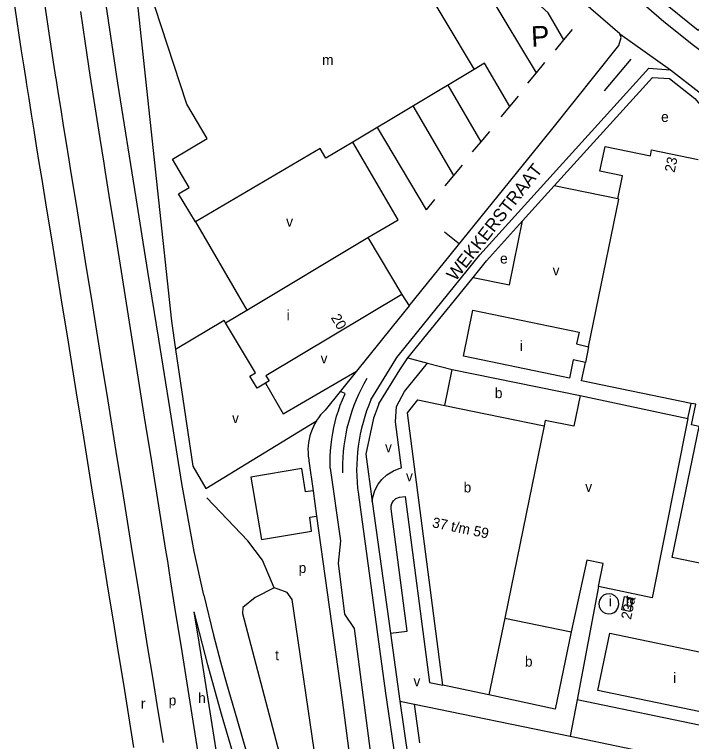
# Model space of a CAD drawing. Extents: x 157699 to 159683, y 381451 to 383293.
# Drawn here: x 157713.1 to 157977.1, y 382628.7 to 382912.1 of the extents above; entities that cross this region are included whole.
import ezdxf

# ---------------------------------------------------------------- set-up
doc = ezdxf.new("R2010")
doc.units = 0
for name, color, linetype in [('BLT_Basislijn', 7, 'Continuous'), ('BLT_Bebouwing', 7, 'Continuous'), ('BLT_Centroide', 7, 'Continuous'), ('BLT_Huisnummer', 7, 'Continuous'), ('BLT_Huisnummer_reeks', 7, 'Continuous'), ('BLT_Onderdoorgang_en_onderverdeling', 7, 'Continuous'), ('BLT_Onderverdeling_panden', 7, 'Continuous'), ('BLT_Straatnaam', 7, 'Continuous'), ('BLT_Tekst_parkeren', 7, 'Continuous'), ('BLT_Vlakafsluiter', 7, 'Continuous')]:
    doc.layers.add(name, color=color, linetype=linetype)

msp = doc.modelspace()

# ---------------------------------------------------------------- linework, layer by layer
at = {"layer": 'BLT_Basislijn'}
for p, q in [((157927.35, 382902.27), (157930.7, 382906.28)), ((157923.99, 382898.25), (157927.35, 382902.27)), ((157916.6, 382889.41), (157919.95, 382893.42)), ((157953.48, 382894.63), (157943.06, 382882.29)), ((157913.25, 382885.39), (157916.6, 382889.41)), ((157895.1, 382862.52), (157882.18, 382884.61)), ((157906.25, 382876.23), (157909.6, 382880.24)), ((157884.44, 382849.34), (157868.59, 382876.47)), ((157902.9, 382872.22), (157906.25, 382876.23)), ((157873.71, 382835.98), (157854.6, 382868.08)), ((157895.1, 382862.52), (157898.45, 382866.53)), ((157891.74, 382858.5), (157895.1, 382862.52)), ((157884.44, 382849.34), (157887.8, 382853.35)), ((157881.09, 382845.32), (157884.44, 382849.34)), ((157948.3, 382840.19), (157923.57, 382845.28)), ((157873.71, 382835.98), (157877.06, 382840)), ((157783.62, 382831.27), (157803.71, 382796.88)), ((157880.8, 382827.41), (157886.6, 382822.68)), ((157864.14, 382803.01), (157867.03, 382798.53)), ((157860.37, 382790.28), (157846.47, 382773.07)), ((157846.47, 382773.07), (157840.08, 382765.15)), ((157840.08, 382765.15), (157834.24, 382757.92)), ((157842.01, 382764.35), (157840.08, 382765.15)), ((157933.67, 382763.53), (157975.66, 382754.55)), ((157975.66, 382754.55), (157976.89, 382760.52)), ((157787.7, 382727.37), (157830.8, 382753.65)), ((157850.07, 382740.75), (157852.61, 382722.31)), ((157827.93, 382738.12), (157829.54, 382726.45)), ((157829.54, 382726.45), (157830.92, 382716.53)), ((157847.21, 382724.81), (157857.82, 382647.47)), ((157852.61, 382722.31), (157859.68, 382670.86)), ((157830.92, 382716.53), (157840.85, 382644.96)), ((157845.48, 382672.76), (157853.96, 382608.2)), ((157859.68, 382670.86), (157863.31, 382644.46)), ((157857.82, 382647.47), (157864.76, 382599.52)), ((157840.85, 382644.96), (157847.02, 382597.39)), ((157863.31, 382644.46), (157869.03, 382643.28)), ((157863.31, 382644.46), (157869.71, 382600.22)), ((157871.21, 382628.11), (157869.03, 382643.28)), ((157869.03, 382643.28), (157929.77, 382630.74)), ((158007.7, 382629.31), (157932.45, 382644.98)), ((157929.77, 382630.74), (157993.12, 382617.66))]:
    msp.add_line(p, q, dxfattribs=at)
for points in [[(157949.07, 382904.54), (157934.04, 382917.51), (157923.29, 382927.29), (157910.32, 382940.07), (157892.3, 382958.54), (157858.2, 382996.52), (157853.38, 383002.06)], [(157916.6, 382889.41), (157873.89, 382960.49), (157865.17, 382970), (157863.48, 382969.01)], [(157757.42, 382949.97), (157774.26, 382792.55), (157775.91, 382781.48)], [(158004.65, 382879.91), (157977.9, 382900), (157966.26, 382909.27), (157938.29, 382933.57)], [(157927.35, 382902.27), (157921.19, 382912.79), (157910, 382923.04), (157909.38, 382922.68)], [(157724.5, 382918.05), (157725.4, 382911.91), (157726.32, 382905.77), (157727.26, 382899.63), (157728.2, 382893.48), (157729.11, 382887.69), (157729.17, 382887.33), (157730.14, 382881.18), (157731.12, 382875.02), (157732.11, 382868.86), (157733.1, 382862.7), (157734.27, 382855.47), (157735.1, 382850.36), (157737.09, 382838.02), (157739.09, 382825.68), (157741.09, 382813.34), (157743.08, 382801.01), (157745.08, 382788.67), (157747.07, 382776.33), (157749.07, 382763.99), (157751.06, 382751.65), (157753.06, 382739.31), (157755.06, 382726.97), (157757.05, 382714.63), (157759.05, 382702.29), (157761.04, 382689.95), (157763.04, 382677.61), (157765.03, 382665.27), (157767.03, 382652.93), (157769.02, 382640.59), (157771.02, 382628.25)], [(157759.67, 382626.41), (157757.67, 382638.75), (157755.68, 382651.09), (157753.68, 382663.43), (157751.69, 382675.77), (157749.69, 382688.11), (157747.69, 382700.45), (157745.7, 382712.79), (157743.7, 382725.13), (157741.71, 382737.47), (157739.71, 382749.81), (157737.72, 382762.15), (157735.72, 382774.49), (157733.72, 382786.83), (157731.73, 382799.17), (157729.73, 382811.51), (157727.74, 382823.85), (157725.74, 382836.19), (157723.75, 382848.53), (157722.92, 382853.63), (157721.75, 382860.87), (157720.76, 382867.04), (157719.77, 382873.2), (157718.78, 382879.37), (157717.81, 382885.54), (157717.75, 382885.91), (157716.84, 382891.71), (157715.89, 382897.88), (157714.95, 382904.05), (157714.03, 382910.23), (157713.12, 382916.4)], [(157786.93, 382685.77), (157783.19, 382702.7), (157778.33, 382729.3), (157773.8, 382757.94), (157769.39, 382785.55), (157765.11, 382811.93), (157762.9, 382825.8), (157760.54, 382840.69), (157753.46, 382885.31), (157748.86, 382915.85)], [(157738.8, 382913.23), (157740.63, 382900.86), (157742.52, 382888.5), (157744.45, 382876.15), (157746.4, 382863.8), (157747.95, 382854.12), (157748.37, 382851.46), (157750.34, 382839.12), (157752.31, 382826.77), (157754.28, 382814.43), (157756.25, 382802.08), (157758.22, 382789.74), (157760.19, 382777.4), (157762.15, 382765.05), (157764.12, 382752.71), (157766.09, 382740.36), (157768.06, 382728.02), (157770.03, 382715.68), (157772, 382703.33), (157772.7, 382698.95), (157773.28, 382695.29), (157773.97, 382690.99), (157775.94, 382678.65), (157777.91, 382666.3), (157779.88, 382653.96), (157781.85, 382641.61), (157783.82, 382629.27), (157785.78, 382616.93)], [(157922.61, 382867.25), (157948.7, 382900), (157949.64, 382903.11), (157949.07, 382904.54)], [(157906.25, 382876.23), (157896.38, 382893.13), (157892.34, 382890.7)], [(157862.66, 382778.99), (157894.49, 382818.41), (157960.42, 382891.16), (157968.91, 382890.58)], [(157968.91, 382890.58), (158002.05, 382864.75), (158022.19, 382850.94), (158036, 382842.3)], [(157923.57, 382845.28), (157961.88, 382887.55), (157968.49, 382887.1)], [(157968.49, 382887.1), (157978.42, 382879.32), (157983.26, 382873.56), (157997.33, 382863.18), (158000.28, 382862.32), (158020.55, 382848.43), (158034.36, 382839.78)], [(157867.03, 382798.53), (157922.61, 382867.25)], [(157850.9, 382825.15), (157862.68, 382832.03), (157844.99, 382862.32)], [(157911.22, 382831.65), (157923.57, 382845.28)], [(157891.9, 382809.63), (157897.15, 382816.13), (157911.22, 382831.65)], [(157891.9, 382809.63), (157906.08, 382806.71), (157911.22, 382831.65)], [(157886.34, 382802.74), (157891.9, 382809.63)], [(157866.52, 382778.2), (157886.34, 382802.74)], [(157867.03, 382798.53), (157860.37, 382790.28)], [(157795.34, 382791.87), (157794.85, 382792.77), (157775.91, 382781.48)], [(157775.91, 382781.48), (157782.66, 382736.01), (157787.7, 382727.37)], [(157860.36, 382775.43), (157862.18, 382778.4), (157862.66, 382778.99)], [(157852.61, 382722.31), (157852.94, 382724.37), (157853.66, 382726.55), (157854.95, 382728.98), (157856.38, 382730.85), (157858.3, 382732.64), (157860.87, 382734.26), (157863.06, 382735.16), (157864, 382735.42), (157861.7, 382753.27), (157862.11, 382759.24), (157865.2, 382765.08), (157874.12, 382776.24)], [(157855.22, 382760.36), (157863.34, 382773.6), (157866.52, 382778.2)], [(157866.52, 382778.2), (157874.12, 382776.24)], [(157874.12, 382776.24), (157883.75, 382773.75)], [(157810.93, 382768.38), (157817.92, 382756.38), (157846.47, 382773.07)], [(157852.09, 382761.95), (157860.36, 382775.43)], [(157850.49, 382770.14), (157849.34, 382768.12), (157848.26, 382766.07), (157847.24, 382763.98), (157846.3, 382761.86), (157845.44, 382759.71), (157844.65, 382757.53), (157843.93, 382755.32), (157843.29, 382753.09), (157842.73, 382750.84), (157842.25, 382748.57), (157841.85, 382746.28), (157841.52, 382743.99), (157841.27, 382741.68), (157841.11, 382739.36), (157841.02, 382737.05), (157841.01, 382734.73), (157841.04, 382733.49)], [(157836.22, 382735.23), (157836.18, 382737.51), (157836.22, 382739.78), (157836.34, 382742.05), (157836.54, 382744.32), (157836.82, 382746.58), (157837.18, 382748.83), (157837.61, 382751.06), (157838.13, 382753.28), (157838.72, 382755.48), (157839.39, 382757.65), (157840.14, 382759.8), (157840.96, 382761.93), (157841.85, 382764.02), (157842.01, 382764.35)], [(157852.09, 382761.95), (157851.2, 382759.77), (157850.39, 382757.56), (157849.65, 382755.33), (157848.99, 382753.07), (157848.4, 382750.79), (157847.89, 382748.49), (157847.46, 382746.18), (157847.11, 382743.85), (157846.84, 382741.51), (157846.65, 382739.17), (157846.54, 382736.82), (157846.5, 382734.46), (157846.55, 382732.11), (157846.68, 382729.76), (157846.89, 382727.41), (157847.18, 382725.08), (157847.21, 382724.81)], [(157855.22, 382760.36), (157854.46, 382758.5), (157853.69, 382756.41), (157853.12, 382754.69), (157850.07, 382740.75)], [(157834.24, 382757.92), (157833.32, 382756.98), (157832.45, 382755.98), (157831.65, 382754.93), (157830.91, 382753.84), (157830.8, 382753.65)], [(157830.8, 382753.65), (157830.24, 382752.71), (157829.64, 382751.53), (157829.11, 382750.32), (157828.65, 382749.08), (157828.27, 382747.82), (157827.97, 382746.54), (157827.75, 382745.23), (157827.61, 382743.92), (157827.54, 382742.6), (157827.56, 382741.29), (157827.65, 382739.97), (157827.83, 382738.66), (157827.93, 382738.12)], [(157975.66, 382754.55), (157961.68, 382684.64), (157940.75, 382689.15)], [(157829.54, 382726.45), (157826.62, 382725.98), (157825.11, 382735.08), (157805.29, 382731.73), (157809.37, 382707.38), (157828.95, 382710.63), (157828.27, 382716.11), (157830.92, 382716.53)], [(157836.22, 382735.23), (157840.27, 382706.91), (157839.3, 382698.23), (157841.81, 382678.35), (157845.48, 382672.76)], [(157814.31, 382688.66), (157809.77, 382699.37), (157804.05, 382706.91), (157788.1, 382723.72)], [(157859.68, 382670.86), (157866.22, 382671.7), (157859.98, 382719.44), (157859.96, 382720.56), (157860.2, 382721.53), (157860.83, 382722.57), (157861.78, 382723.39), (157863.26, 382723.91), (157865.48, 382724.2), (157874.89, 382651.7), (157880.13, 382650.62)], [(157940.75, 382689.15), (157942.68, 382698.1), (157936.29, 382699.4), (157930.14, 382671.48)], [(157814.31, 382688.66), (157806.99, 382684.84), (157802.17, 382680.96), (157802.03, 382678.58), (157833.39, 382559.57), (157852.12, 382424.4), (157856.21, 382403.71), (157863.37, 382370.92), (157866.2, 382371.54)], [(157866.2, 382371.54), (157863.56, 382386.33), (157840.74, 382543.08), (157839.7, 382551.81), (157840.08, 382554.13), (157840.98, 382555.96), (157842.28, 382555.94), (157841.59, 382560.09), (157838.61, 382565.98), (157821.37, 382684.05), (157819.38, 382686.74), (157815.85, 382688.1), (157814.31, 382688.66)], [(157940.75, 382689.15), (157932.45, 382644.98)], [(157786.93, 382685.77), (157790.71, 382670.14), (157793.44, 382659.75), (157795.78, 382651.33), (157798.88, 382640.71), (157804.35, 382621.87), (157806.97, 382612.47), (157811.94, 382593.14), (157816.3, 382574.16), (157820.46, 382553.59), (157827.25, 382512.59), (157837.82, 382445.33), (157840.91, 382425.36), (157842.49, 382416.11), (157844.46, 382406.06)], [(157814.33, 382483.41), (157812.61, 382494.6), (157810.67, 382506.97), (157810.41, 382508.58), (157808.7, 382519.32), (157806.73, 382531.66), (157804.76, 382544), (157802.79, 382556.35), (157800.82, 382568.69), (157798.85, 382581.04), (157796.88, 382593.38), (157794.91, 382605.72), (157792.94, 382618.07), (157790.97, 382630.41), (157789.01, 382642.76), (157787.04, 382655.1), (157785.07, 382667.44), (157783.19, 382679.23)], [(157816.09, 382549.38), (157811.54, 382571.58), (157807.5, 382589.41), (157804.61, 382601.15), (157799.45, 382620.43), (157793.85, 382639.38), (157788.43, 382658.53), (157783.19, 382679.23)], [(157932.45, 382644.98), (157929.77, 382630.74)]]:
    msp.add_lwpolyline(points, dxfattribs=at)
at = {"layer": 'BLT_Bebouwing'}
for p, q in [((157880.88, 382759.73), (157883.75, 382773.75)), ((157883.75, 382773.75), (157933.67, 382763.53)), ((157919.63, 382751.76), (157904.25, 382676.8)), ((157945.23, 382670.92), (158002.95, 382658.94))]:
    msp.add_line(p, q, dxfattribs=at)
for points in [[(157783.62, 382831.27), (157777.07, 382842.25), (157781.19, 382844.72), (157774.73, 382855.69), (157788.28, 382863.77), (157780.24, 382877.19), (157767.77, 382915.25), (157785.92, 382926.14), (157767.81, 382956.5), (157780.62, 382964.23), (157786.04, 382955.13), (157837.7, 382985.98)], [(157837.7, 382985.98), (157861.29, 382946.4), (157865.96, 382949.15), (157872.1, 382938.88), (157867.46, 382936.08), (157870.72, 382930.6), (157869.09, 382929.61), (157892.34, 382890.7)], [(157980.27, 382906.59), (157979.68, 382905.87), (157964.22, 382918.47), (157977.09, 382934.26), (157974.11, 382936.69), (157978.79, 382942.44), (157981.77, 382940), (157982.5, 382940.9)], [(157892.34, 382890.7), (157844.99, 382862.32)], [(157844.99, 382862.32), (157834.53, 382856.05), (157832.24, 382859.88), (157783.62, 382831.27)], [(157948.3, 382840.19), (157950.14, 382849.17), (157941.39, 382850.97), (157943.37, 382860.61), (157961.04, 382856.97), (157961.51, 382859.29), (157979.64, 382855.59)], [(157936.96, 382782.6), (157948.8, 382840.09), (157948.3, 382840.19)], [(157803.71, 382796.88), (157850.9, 382825.15)], [(157850.9, 382825.15), (157864.14, 382803.01)], [(157864.14, 382803.01), (157811.12, 382771.27), (157812.35, 382769.24), (157810.93, 382768.38)], [(157795.34, 382791.87), (157803.71, 382796.88)], [(157935.69, 382776.47), (157930.99, 382777.45), (157929.51, 382770.3), (157888.12, 382778.88), (157891.84, 382796.81), (157933.33, 382788.22), (157932.28, 382783.67), (157936.96, 382782.6)], [(157810.93, 382768.38), (157807.72, 382766.43), (157804.86, 382771.11), (157807.02, 382772.39), (157795.34, 382791.87)], [(157976.89, 382760.52), (157934.22, 382769.32), (157935.69, 382776.47)], [(157880.13, 382650.62), (157866.39, 382756.76), (157870.41, 382761.89), (157880.88, 382759.73)], [(157933.67, 382763.53), (157931.22, 382751.56), (157920.05, 382753.85), (157919.63, 382751.76)], [(158011.13, 382691.79), (157969.49, 382700.36), (157980.02, 382751.51), (157977.09, 382752.11), (157978.74, 382760.14), (157976.89, 382760.52)], [(157904.25, 382676.8), (157930.14, 382671.48)], [(157930.14, 382671.48), (157923.9, 382641.27), (157898.11, 382646.91)], [(157940.6, 382648.6), (157945.23, 382670.92)], [(157898.11, 382646.91), (157880.13, 382650.62)], [(157993.05, 382637.71), (157940.6, 382648.6)]]:
    msp.add_lwpolyline(points, dxfattribs=at)
for points in [[(157948.62, 382683.53), (157948.1, 382684.6), (157947.2, 382685.52), (157946.07, 382686.1), (157944.93, 382686.29), (157943.84, 382686.15), (157942.78, 382685.68), (157941.84, 382684.85), (157941.2, 382683.75), (157940.95, 382682.5), (157941.1, 382681.28), (157941.61, 382680.17), (157942.45, 382679.27), (157943.43, 382678.7), (157944.57, 382678.44), (157945.89, 382678.56), (157946.9, 382678.99), (157947.76, 382679.69), (157948.4, 382680.61), (157948.79, 382682.05)], [(157950.93, 382685.17), (157954.1, 382684.51), (157953.03, 382679.4), (157949.87, 382680.05)]]:
    msp.add_lwpolyline(points, close=True, dxfattribs=at)
at = {"layer": 'BLT_Onderdoorgang_en_onderverdeling'}
for p, q in [((157880.88, 382759.73), (157919.63, 382751.76)), ((157904.25, 382676.8), (157898.11, 382646.91))]:
    msp.add_line(p, q, dxfattribs=at)
at = {"layer": 'BLT_Onderverdeling_panden'}
msp.add_line((157936.96, 382782.6), (157935.69, 382776.47), dxfattribs=at)
at = {"layer": 'BLT_Vlakafsluiter'}
msp.add_line((157949.07, 382904.54), (157968.91, 382890.58), dxfattribs=at)

# ---------------------------------------------------------------- texts
at = {"layer": 'BLT_Centroide'}
for s, p in [('m', (157833.04, 382892.43)), ('e', (157965.22, 382870.22)), ('v', (157819.04, 382829.4)), ('e', (157902.42, 382815.02)), ('v', (157922.93, 382810.4)), ('i', (157819.23, 382792.89)), ('i', (157910.11, 382780.93)), ('v', (157832.47, 382776.08)), ('b', (157900.4, 382762.56)), ('v', (157797.95, 382752.83)), ('v', (157857.59, 382741.47)), ('v', (157865.76, 382730.14)), ('b', (157888.22, 382725.78)), ('v', (157935.64, 382726.01)), ('p', (157823.9, 382694.39)), ('i', (157944.87, 382681.37)), ('b', (157951.47, 382681.36)), ('t', (157814.75, 382660.38)), ('b', (157912.12, 382657.89)), ('i', (157969.92, 382651.54)), ('v', (157868.68, 382650.24)), ('p', (157773.23, 382642.77)), ('h', (157784.72, 382643.65)), ('r', (157762.38, 382641.52))]:
    msp.add_text(s, height=4, dxfattribs=at).set_placement(p)
at = {"layer": 'BLT_Huisnummer'}
for s, p in [('23', (157970.45, 382850.28)), ('23a', (157953.46, 382676))]:
    msp.add_text(s, height=4, rotation=78.3568, dxfattribs=at).set_placement(p)
at = {"layer": 'BLT_Huisnummer_reeks'}
for s, rotation, p in [('20', 300.8987, (157836.34, 382793.92)), ('37 t/m 59', 348.3713, (157875.74, 382712.27))]:
    msp.add_text(s, height=4, rotation=rotation, dxfattribs=at).set_placement(p)
at = {"layer": 'BLT_Straatnaam'}
msp.add_text('WEKKERSTRAAT', height=5, rotation=51.838, dxfattribs=at).set_placement((157885.07, 382807.87))
at = {"layer": 'BLT_Tekst_parkeren'}
msp.add_text('P', height=8, rotation=2.8586, dxfattribs=at).set_placement((157914.72, 382899.47))

doc.saveas('drawing.dxf')
